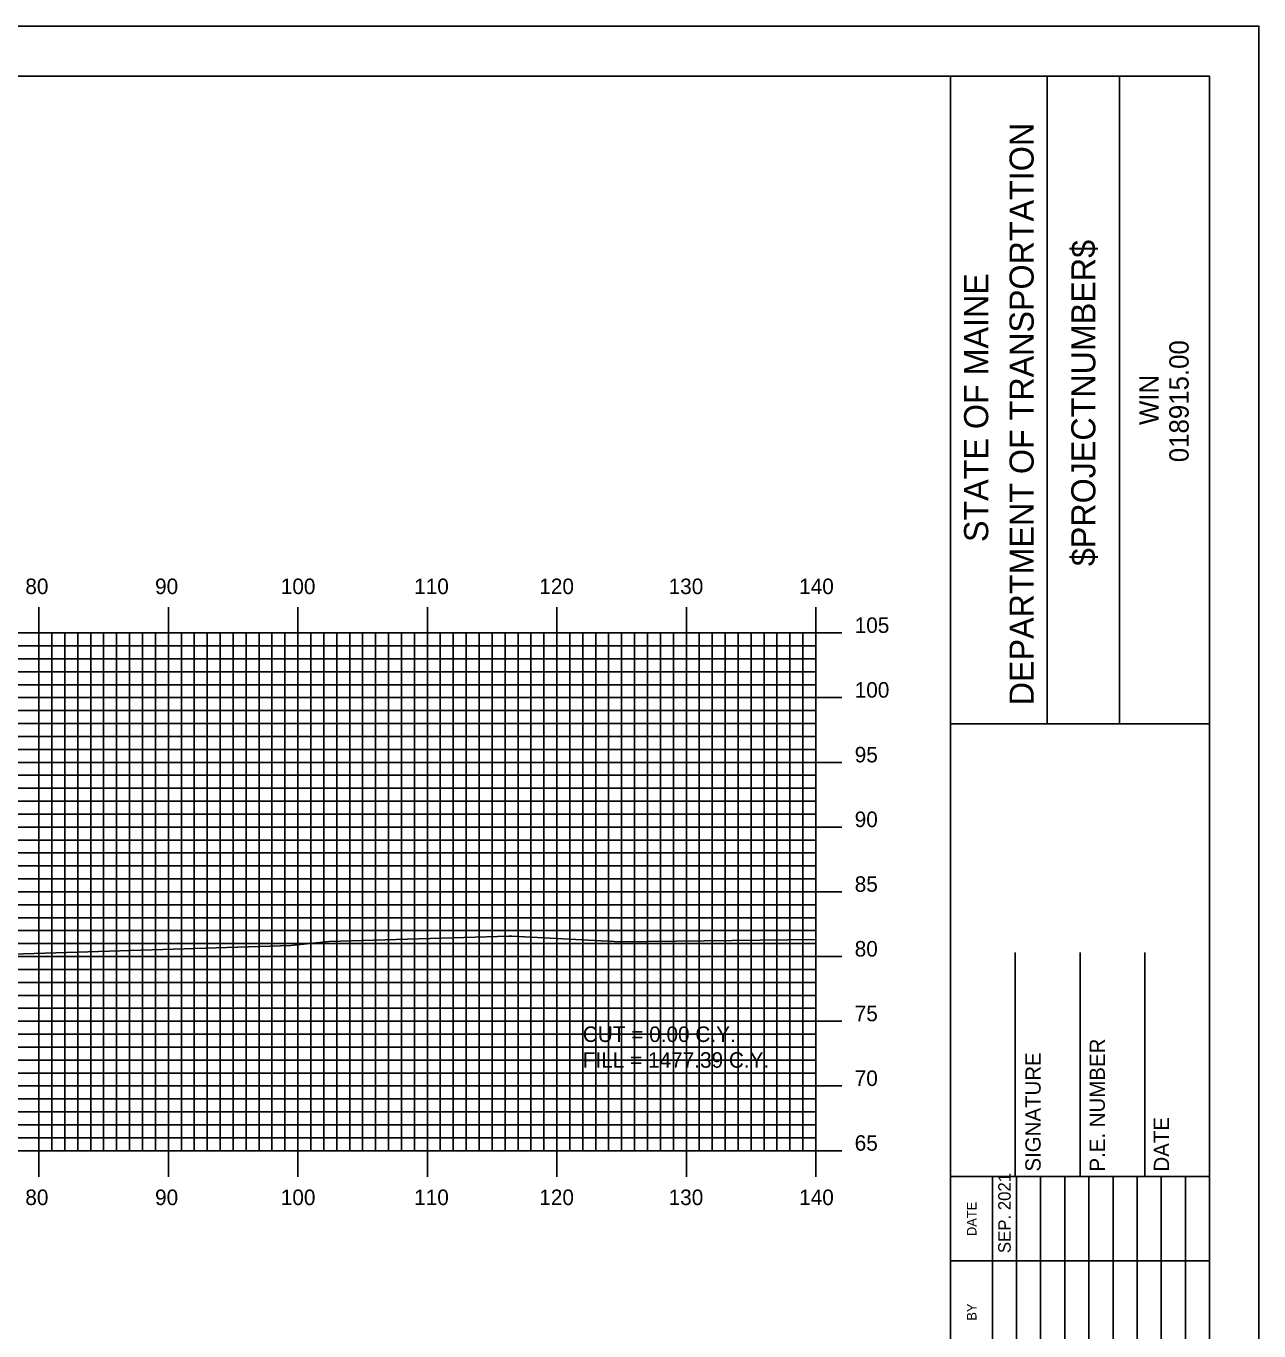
# Model space of a CAD drawing. Extents: x 852936 to 853279, y 364366 to 364586.
# Drawn here: x 853180.7 to 853275.9, y 364484.9 to 364585.7 of the extents above; entities that cross this region are included whole.
import ezdxf

# ---------------------------------------------------------------- set-up
doc = ezdxf.new("R2010")
doc.units = 0
for name, color, linetype in [('BORDER', 7, 'Continuous'), ('D_Text_Standard', 7, 'Continuous'), ('H_V ANNOTATION', 7, 'Continuous'), ('MAJOR', 7, 'Continuous'), ('MINOR', 7, 'Continuous'), ('PLOT BOUNDARY', 7, 'Continuous'), ('S_Roadway_Centerline', 7, 'Continuous')]:
    doc.layers.add(name, color=color, linetype=linetype)

msp = doc.modelspace()

# ---------------------------------------------------------------- linework, layer by layer
at = {"layer": 'BORDER'}
for p, q in [((853252.09, 364371.79), (853252.09, 364581.79)), ((853259.55, 364531.78), (853259.55, 364581.78)), ((853265.14, 364531.78), (853265.14, 364581.78)), ((853252.09, 364531.78), (853272.09, 364531.78)), ((853257.09, 364496.79), (853257.09, 364514.09)), ((853262.09, 364496.79), (853262.09, 364514.09)), ((853267.09, 364496.79), (853267.09, 364514.09)), ((853252.09, 364496.79), (853272.09, 364496.79))]:
    msp.add_line(p, q, dxfattribs=at)
msp.add_lwpolyline([(852952.09, 364371.79), (853272.09, 364371.79), (853272.09, 364581.79), (852952.09, 364581.79)], close=True, dxfattribs=at)
for points in [[(853255.32, 364490.29), (853255.32, 364496.79)], [(853257.19, 364461.8), (853257.19, 364496.79)], [(853259.05, 364496.79), (853259.05, 364461.8)], [(853260.91, 364461.8), (853260.91, 364496.79)], [(853262.78, 364461.8), (853262.78, 364496.79)], [(853264.64, 364461.8), (853264.64, 364496.79)], [(853266.5, 364461.8), (853266.5, 364496.79)], [(853268.37, 364461.8), (853268.37, 364496.79)], [(853270.23, 364461.8), (853270.23, 364496.79)], [(853255.32, 364461.8), (853255.32, 364495.38)], [(853252.09, 364490.29), (853272.09, 364490.29)]]:
    msp.add_lwpolyline(points, dxfattribs=at)
at = {"layer": 'MAJOR'}
for p, q in [((853181.69, 364540.79), (853181.69, 364538.79)), ((853191.69, 364540.79), (853191.69, 364538.79)), ((853201.69, 364540.79), (853201.69, 364538.79)), ((853211.69, 364540.79), (853211.69, 364538.79)), ((853221.69, 364540.79), (853221.69, 364538.79)), ((853231.69, 364540.79), (853231.69, 364538.79)), ((853241.69, 364540.79), (853241.69, 364538.79)), ((852961.69, 364538.79), (853241.69, 364538.79)), ((852961.69, 364538.79), (853241.69, 364538.79)), ((853181.69, 364498.79), (853181.69, 364538.79)), ((853191.69, 364498.79), (853191.69, 364538.79)), ((853201.69, 364498.79), (853201.69, 364538.79)), ((853211.69, 364498.79), (853211.69, 364538.79)), ((853221.69, 364498.79), (853221.69, 364538.79)), ((853231.69, 364498.79), (853231.69, 364538.79)), ((853243.7, 364538.79), (853239.69, 364538.79)), ((853241.69, 364498.79), (853241.69, 364538.79)), ((853241.69, 364498.79), (853241.69, 364538.79)), ((852961.69, 364533.79), (853241.69, 364533.79)), ((853243.7, 364533.79), (853239.69, 364533.79)), ((852961.69, 364528.79), (853241.69, 364528.79)), ((853243.7, 364528.79), (853239.69, 364528.79)), ((852961.69, 364523.79), (853241.69, 364523.79)), ((853243.7, 364523.79), (853239.69, 364523.79)), ((852961.69, 364518.79), (853241.69, 364518.79)), ((853243.7, 364518.79), (853239.69, 364518.79)), ((852961.69, 364513.79), (853241.69, 364513.79)), ((853243.7, 364513.79), (853239.69, 364513.79)), ((852961.69, 364508.79), (853241.69, 364508.79)), ((853243.7, 364508.79), (853239.69, 364508.79)), ((852961.69, 364503.79), (853241.69, 364503.79)), ((853243.7, 364503.79), (853239.69, 364503.79)), ((852961.69, 364498.79), (853241.69, 364498.79)), ((852961.69, 364498.79), (853241.69, 364498.79)), ((853181.69, 364496.78), (853181.69, 364498.79)), ((853191.69, 364496.78), (853191.69, 364498.79)), ((853201.69, 364496.78), (853201.69, 364498.79)), ((853211.69, 364496.78), (853211.69, 364498.79)), ((853221.69, 364496.78), (853221.69, 364498.79)), ((853231.69, 364496.78), (853231.69, 364498.79)), ((853243.7, 364498.79), (853239.69, 364498.79)), ((853241.69, 364496.78), (853241.69, 364498.79))]:
    msp.add_line(p, q, dxfattribs=at)
at = {"layer": 'MINOR'}
for p, q in [((853182.69, 364498.79), (853182.69, 364538.79)), ((853183.69, 364498.79), (853183.69, 364538.79)), ((853184.69, 364498.79), (853184.69, 364538.79)), ((853185.69, 364498.79), (853185.69, 364538.79)), ((853186.69, 364498.79), (853186.69, 364538.79)), ((853187.69, 364498.79), (853187.69, 364538.79)), ((853188.69, 364498.79), (853188.69, 364538.79)), ((853189.69, 364498.79), (853189.69, 364538.79)), ((853190.69, 364498.79), (853190.69, 364538.79)), ((853192.69, 364498.79), (853192.69, 364538.79)), ((853193.69, 364498.79), (853193.69, 364538.79)), ((853194.69, 364498.79), (853194.69, 364538.79)), ((853195.69, 364498.79), (853195.69, 364538.79)), ((853196.69, 364498.79), (853196.69, 364538.79)), ((853197.69, 364498.79), (853197.69, 364538.79)), ((853198.69, 364498.79), (853198.69, 364538.79)), ((853199.69, 364498.79), (853199.69, 364538.79)), ((853200.69, 364498.79), (853200.69, 364538.79)), ((853202.69, 364498.79), (853202.69, 364538.79)), ((853203.69, 364498.79), (853203.69, 364538.79)), ((853204.69, 364498.79), (853204.69, 364538.79)), ((853205.69, 364498.79), (853205.69, 364538.79)), ((853206.69, 364498.79), (853206.69, 364538.79)), ((853207.69, 364498.79), (853207.69, 364538.79)), ((853208.69, 364498.79), (853208.69, 364538.79)), ((853209.69, 364498.79), (853209.69, 364538.79)), ((853210.69, 364498.79), (853210.69, 364538.79)), ((853212.69, 364498.79), (853212.69, 364538.79)), ((853213.69, 364498.79), (853213.69, 364538.79)), ((853214.69, 364498.79), (853214.69, 364538.79)), ((853215.69, 364498.79), (853215.69, 364538.79)), ((853216.69, 364498.79), (853216.69, 364538.79)), ((853217.69, 364498.79), (853217.69, 364538.79)), ((853218.69, 364498.79), (853218.69, 364538.79)), ((853219.69, 364498.79), (853219.69, 364538.79)), ((853220.69, 364498.79), (853220.69, 364538.79)), ((853222.69, 364498.79), (853222.69, 364538.79)), ((853223.69, 364498.79), (853223.69, 364538.79)), ((853224.69, 364498.79), (853224.69, 364538.79)), ((853225.69, 364498.79), (853225.69, 364538.79)), ((853226.69, 364498.79), (853226.69, 364538.79)), ((853227.69, 364498.79), (853227.69, 364538.79)), ((853228.69, 364498.79), (853228.69, 364538.79)), ((853229.69, 364498.79), (853229.69, 364538.79)), ((853230.69, 364498.79), (853230.69, 364538.79)), ((853232.69, 364498.79), (853232.69, 364538.79)), ((853233.69, 364498.79), (853233.69, 364538.79)), ((853234.69, 364498.79), (853234.69, 364538.79)), ((853235.69, 364498.79), (853235.69, 364538.79)), ((853236.69, 364498.79), (853236.69, 364538.79)), ((853237.69, 364498.79), (853237.69, 364538.79)), ((853238.69, 364498.79), (853238.69, 364538.79)), ((853239.69, 364498.79), (853239.69, 364538.79)), ((853240.69, 364498.79), (853240.69, 364538.79)), ((852961.69, 364537.79), (853241.69, 364537.79)), ((853241.69, 364537.79), (853239.69, 364537.79)), ((852961.69, 364536.79), (853241.69, 364536.79)), ((853241.69, 364536.79), (853239.69, 364536.79)), ((852961.69, 364535.79), (853241.69, 364535.79)), ((853241.69, 364535.79), (853239.69, 364535.79)), ((852961.69, 364534.79), (853241.69, 364534.79)), ((853241.69, 364534.79), (853239.69, 364534.79)), ((852961.69, 364532.79), (853241.69, 364532.79)), ((853241.69, 364532.79), (853239.69, 364532.79)), ((852961.69, 364531.79), (853241.69, 364531.79)), ((853241.69, 364531.79), (853239.69, 364531.79)), ((852961.69, 364530.79), (853241.69, 364530.79)), ((853241.69, 364530.79), (853239.69, 364530.79)), ((852961.69, 364529.79), (853241.69, 364529.79)), ((853241.69, 364529.79), (853239.69, 364529.79)), ((852961.69, 364527.79), (853241.69, 364527.79)), ((853241.69, 364527.79), (853239.69, 364527.79)), ((852961.69, 364526.79), (853241.69, 364526.79)), ((853241.69, 364526.79), (853239.69, 364526.79)), ((852961.69, 364525.79), (853241.69, 364525.79)), ((853241.69, 364525.79), (853239.69, 364525.79)), ((852961.69, 364524.79), (853241.69, 364524.79)), ((853241.69, 364524.79), (853239.69, 364524.79)), ((852961.69, 364522.79), (853241.69, 364522.79)), ((853241.69, 364522.79), (853239.69, 364522.79)), ((852961.69, 364521.79), (853241.69, 364521.79)), ((853241.69, 364521.79), (853239.69, 364521.79)), ((852961.69, 364520.79), (853241.69, 364520.79)), ((853241.69, 364520.79), (853239.69, 364520.79)), ((852961.69, 364519.79), (853241.69, 364519.79)), ((853241.69, 364519.79), (853239.69, 364519.79)), ((852961.69, 364517.79), (853241.69, 364517.79)), ((853241.69, 364517.79), (853239.69, 364517.79)), ((852961.69, 364516.79), (853241.69, 364516.79)), ((853241.69, 364516.79), (853239.69, 364516.79)), ((852961.69, 364515.79), (853241.69, 364515.79)), ((853241.69, 364515.79), (853239.69, 364515.79)), ((852961.69, 364514.79), (853241.69, 364514.79)), ((853241.69, 364514.79), (853239.69, 364514.79)), ((852961.69, 364512.79), (853241.69, 364512.79)), ((853241.69, 364512.79), (853239.69, 364512.79)), ((852961.69, 364511.79), (853241.69, 364511.79)), ((853241.69, 364511.79), (853239.69, 364511.79)), ((852961.69, 364510.79), (853241.69, 364510.79)), ((853241.69, 364510.79), (853239.69, 364510.79)), ((852961.69, 364509.79), (853241.69, 364509.79)), ((853241.69, 364509.79), (853239.69, 364509.79)), ((852961.69, 364507.79), (853241.69, 364507.79)), ((853241.69, 364507.79), (853239.69, 364507.79)), ((852961.69, 364506.79), (853241.69, 364506.79)), ((853241.69, 364506.79), (853239.69, 364506.79)), ((852961.69, 364505.79), (853241.69, 364505.79)), ((853241.69, 364505.79), (853239.69, 364505.79)), ((852961.69, 364504.79), (853241.69, 364504.79)), ((853241.69, 364504.79), (853239.69, 364504.79)), ((852961.69, 364502.79), (853241.69, 364502.79)), ((853241.69, 364502.79), (853239.69, 364502.79)), ((852961.69, 364501.79), (853241.69, 364501.79)), ((853241.69, 364501.79), (853239.69, 364501.79)), ((852961.69, 364500.79), (853241.69, 364500.79)), ((853241.69, 364500.79), (853239.69, 364500.79)), ((852961.69, 364499.79), (853241.69, 364499.79)), ((853241.69, 364499.79), (853239.69, 364499.79))]:
    msp.add_line(p, q, dxfattribs=at)
at = {"layer": 'PLOT BOUNDARY'}
msp.add_lwpolyline([(852935.9, 364365.67), (853275.9, 364365.67), (853275.9, 364585.67), (852935.9, 364585.67)], close=True, dxfattribs=at)
at = {"layer": 'S_Roadway_Centerline'}
msp.add_lwpolyline([(853178.86, 364513.96), (853201.17, 364514.65), (853204.07, 364514.95), (853217.99, 364515.36), (853218.12, 364515.36), (853218.21, 364515.36), (853226.6, 364514.93), (853241.69, 364515.1)], dxfattribs=at)

# ---------------------------------------------------------------- texts
at = {"layer": 'BORDER'}
for s, height, p in [('DEPARTMENT OF TRANSPORTATION', 1.8635, (853258.51, 364533.2)), ('$PROJECTNUMBER$', 1.8635, (853263.28, 364543.95)), ('STATE OF MAINE', 1.8635, (853255, 364545.81)), ('018915.00', 1.491, (853270.48, 364551.98)), ('WIN', 1.491, (853268.16, 364554.85)), ('P.E. NUMBER', 1.1811, (853264.01, 364497.18)), ('SIGNATURE', 1.181, (853259.05, 364497.18)), ('DATE', 1.181, (853268.97, 364497.18)), ('SEP. 2021', 0.969, (853256.74, 364490.88)), ('DATE', 0.743, (853254.1, 364492.2)), ('BY', 0.743, (853254.1, 364485.66))]:
    msp.add_text(s, height=height, rotation=90, dxfattribs=at).set_placement(p)
at = {"layer": 'D_Text_Standard'}
for s, p in [('CUT = 0.00 C.Y.', (853223.69, 364507.19)), ('FILL = 1477.39 C.Y.', (853223.69, 364505.2))]:
    msp.add_text(s, height=1.2, dxfattribs=at).set_placement(p)
at = {"layer": 'H_V ANNOTATION'}
for s, p in [('80', (853180.64, 364541.79)), ('90', (853190.66, 364541.79)), ('100', (853200.37, 364541.79)), ('110', (853210.67, 364541.79)), ('120', (853220.33, 364541.79)), ('130', (853230.32, 364541.79)), ('140', (853240.4, 364541.79)), ('105', (853244.69, 364538.79)), ('100', (853244.69, 364533.79)), ('95', (853244.69, 364528.79)), ('90', (853244.69, 364523.79)), ('85', (853244.69, 364518.79)), ('80', (853244.69, 364513.79)), ('75', (853244.69, 364508.79)), ('70', (853244.69, 364503.79)), ('65', (853244.69, 364498.79)), ('80', (853180.64, 364494.59)), ('90', (853190.66, 364494.59)), ('100', (853200.37, 364494.59)), ('110', (853210.67, 364494.59)), ('120', (853220.33, 364494.59)), ('130', (853230.32, 364494.59)), ('140', (853240.4, 364494.59))]:
    msp.add_text(s, height=1.2, dxfattribs=at).set_placement(p)

doc.saveas('drawing.dxf')
